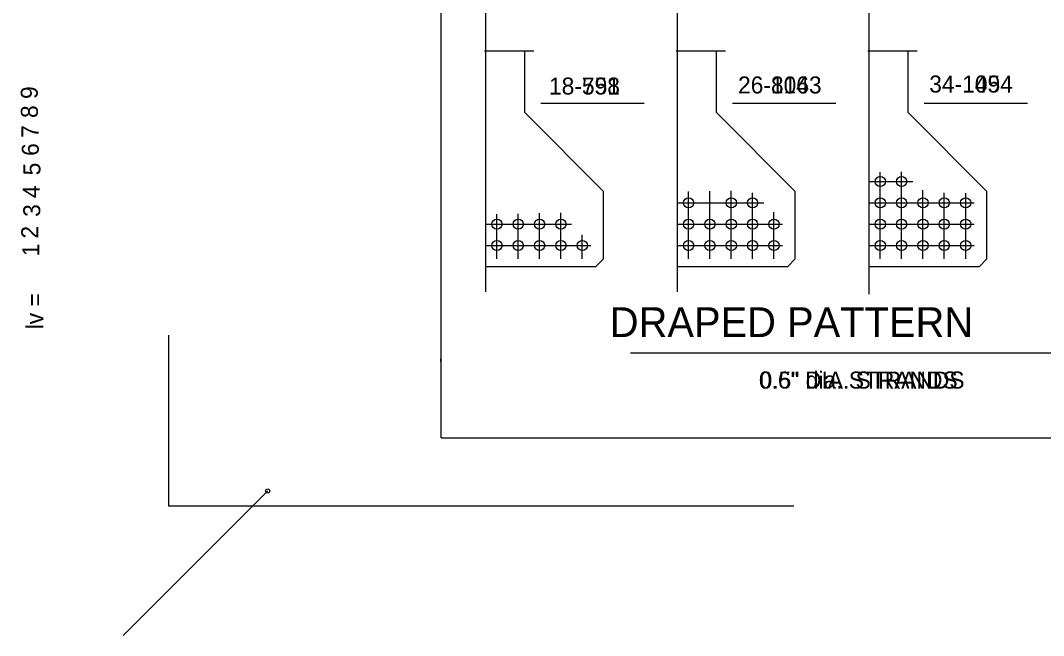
# Model space of a CAD drawing. Extents: x 1005.3 to 1101.9, y 1996.5 to 2073.3.
# Drawn here: x 1005.62 to 1025.64, y 2008.29 to 2020.32 of the extents above; entities that cross this region are included whole.
import ezdxf

# ---------------------------------------------------------------- set-up
doc = ezdxf.new("R2010")
doc.units = 0
for name, color, linetype in [('Level 1', 7, 'Continuous'), ('Level 2', 7, 'Continuous'), ('Level 3', 7, 'Continuous'), ('Level 4', 7, 'Continuous'), ('Level 49', 7, 'Continuous'), ('Level 5', 7, 'Continuous'), ('Level 6', 7, 'Continuous'), ('Level 7', 7, 'Continuous'), ('Level 8', 7, 'Continuous'), ('Level 9', 7, 'Continuous')]:
    doc.layers.add(name, color=color, linetype=linetype)

msp = doc.modelspace()

# ---------------------------------------------------------------- linework, layer by layer
at = {"layer": 'Level 1'}
for p, q in [((1013.852, 2012.158), (1013.852, 2068.156)), ((1008.518, 2014.165), (1008.518, 2010.825)), ((1013.84, 2013.698), (1013.84, 2013.64)), ((1013.852, 2012.158), (1097.517, 2012.158)), ((1008.518, 2010.825), (1020.752, 2010.825))]:
    msp.add_line(p, q, dxfattribs=at)
at = {"layer": 'Level 2'}
for p, q in [((1017.555, 2013.82), (1026.098, 2013.82)), ((1007.632, 2008.287), (1010.461, 2011.116))]:
    msp.add_line(p, q, dxfattribs=at)
at = {"layer": 'Level 49'}
msp.add_circle((1010.46, 2011.116), 0.0405, dxfattribs=at)
at = {"layer": 'Level 8'}
for p, q in [((1014.726, 2015.012), (1014.726, 2037.24)), ((1018.476, 2015.012), (1018.476, 2037.24)), ((1022.226, 2014.966), (1022.226, 2037.289)), ((1014.703, 2019.726), (1015.668, 2019.726)), ((1015.488, 2018.518), (1015.488, 2019.719)), ((1018.453, 2019.726), (1019.418, 2019.726)), ((1019.238, 2018.518), (1019.238, 2019.719)), ((1022.203, 2019.726), (1023.168, 2019.726)), ((1022.988, 2018.518), (1022.988, 2019.719)), ((1015.804, 2018.702), (1017.824, 2018.702)), ((1019.554, 2018.702), (1021.574, 2018.702)), ((1023.304, 2018.702), (1025.324, 2018.702)), ((1017.032, 2016.973), (1015.488, 2018.518)), ((1020.782, 2016.973), (1019.238, 2018.518)), ((1024.532, 2016.973), (1022.988, 2018.518)), ((1022.226, 2017.172), (1023.082, 2017.172)), ((1022.445, 2015.658), (1022.445, 2017.352)), ((1022.862, 2015.658), (1022.862, 2017.358)), ((1017.032, 2015.658), (1017.032, 2016.973)), ((1018.695, 2015.658), (1018.695, 2016.976)), ((1019.112, 2015.658), (1019.112, 2016.982)), ((1019.53, 2015.658), (1019.53, 2016.989)), ((1020.782, 2015.658), (1020.782, 2016.973)), ((1023.28, 2015.658), (1023.28, 2017)), ((1024.532, 2015.658), (1024.532, 2016.973)), ((1019.947, 2015.658), (1019.947, 2016.952)), ((1023.697, 2015.658), (1023.697, 2016.952)), ((1024.115, 2015.658), (1024.115, 2016.944)), ((1018.476, 2016.754), (1020.168, 2016.754)), ((1020.365, 2015.658), (1020.365, 2016.57)), ((1022.226, 2016.754), (1024.283, 2016.754)), ((1014.945, 2015.658), (1014.945, 2016.529)), ((1015.362, 2015.658), (1015.362, 2016.538)), ((1015.78, 2015.658), (1015.78, 2016.548)), ((1016.197, 2015.658), (1016.197, 2016.557)), ((1014.726, 2016.337), (1016.401, 2016.337)), ((1018.476, 2016.337), (1020.533, 2016.337)), ((1022.226, 2016.337), (1024.283, 2016.337)), ((1016.615, 2015.658), (1016.615, 2016.127)), ((1014.726, 2015.919), (1016.783, 2015.919)), ((1018.476, 2015.919), (1020.533, 2015.919)), ((1022.226, 2015.919), (1024.283, 2015.919)), ((1016.876, 2015.501), (1017.032, 2015.658)), ((1020.626, 2015.501), (1020.782, 2015.658)), ((1024.376, 2015.501), (1024.532, 2015.658)), ((1016.876, 2015.501), (1014.726, 2015.501)), ((1020.626, 2015.501), (1018.476, 2015.501)), ((1024.376, 2015.501), (1022.226, 2015.501))]:
    msp.add_line(p, q, dxfattribs=at)
for centre in [(1022.445, 2017.172), (1022.862, 2017.172), (1018.695, 2016.754), (1019.53, 2016.754), (1019.947, 2016.754), (1022.445, 2016.754), (1022.862, 2016.754), (1023.28, 2016.754), (1023.697, 2016.754), (1024.115, 2016.754), (1014.945, 2016.337), (1015.362, 2016.337), (1015.78, 2016.337), (1016.197, 2016.337), (1018.695, 2016.337), (1019.112, 2016.337), (1019.53, 2016.337), (1019.947, 2016.337), (1020.365, 2016.337), (1022.445, 2016.337), (1022.862, 2016.337), (1023.28, 2016.337), (1023.697, 2016.337), (1024.115, 2016.337), (1014.945, 2015.919), (1015.362, 2015.919), (1015.78, 2015.919), (1016.197, 2015.919), (1016.615, 2015.919), (1018.695, 2015.919), (1019.112, 2015.919), (1019.53, 2015.919), (1019.947, 2015.919), (1020.365, 2015.919), (1022.445, 2015.919), (1022.862, 2015.919), (1023.28, 2015.919), (1023.697, 2015.919), (1024.115, 2015.919)]:
    msp.add_circle(centre, 0.0996, dxfattribs=at)
at = {"layer": 'Level 9'}
for p, q in [((1014.726, 2015.012), (1014.726, 2037.24)), ((1018.476, 2015.012), (1018.476, 2037.24)), ((1022.226, 2014.966), (1022.226, 2037.289)), ((1014.703, 2019.726), (1015.668, 2019.726)), ((1015.488, 2018.518), (1015.488, 2019.719)), ((1018.453, 2019.726), (1019.418, 2019.726)), ((1019.238, 2018.518), (1019.238, 2019.719)), ((1022.203, 2019.726), (1023.168, 2019.726)), ((1022.988, 2018.518), (1022.988, 2019.719)), ((1015.804, 2018.702), (1017.824, 2018.702)), ((1019.554, 2018.702), (1021.574, 2018.702)), ((1023.304, 2018.702), (1025.324, 2018.702)), ((1017.032, 2016.973), (1015.488, 2018.518)), ((1020.782, 2016.973), (1019.238, 2018.518)), ((1024.532, 2016.973), (1022.988, 2018.518)), ((1022.226, 2017.172), (1023.082, 2017.172)), ((1022.445, 2015.658), (1022.445, 2017.352)), ((1022.862, 2015.658), (1022.862, 2017.358)), ((1017.032, 2015.658), (1017.032, 2016.973)), ((1018.695, 2015.658), (1018.695, 2016.976)), ((1019.112, 2015.658), (1019.112, 2016.982)), ((1019.53, 2015.658), (1019.53, 2016.989)), ((1020.782, 2015.658), (1020.782, 2016.973)), ((1023.28, 2015.658), (1023.28, 2017)), ((1024.532, 2015.658), (1024.532, 2016.973)), ((1019.947, 2015.658), (1019.947, 2016.952)), ((1023.697, 2015.658), (1023.697, 2016.952)), ((1024.115, 2015.658), (1024.115, 2016.944)), ((1018.476, 2016.754), (1020.168, 2016.754)), ((1020.365, 2015.658), (1020.365, 2016.57)), ((1022.226, 2016.754), (1024.283, 2016.754)), ((1014.945, 2015.658), (1014.945, 2016.529)), ((1015.362, 2015.658), (1015.362, 2016.538)), ((1015.78, 2015.658), (1015.78, 2016.548)), ((1016.197, 2015.658), (1016.197, 2016.557)), ((1014.726, 2016.337), (1016.401, 2016.337)), ((1018.476, 2016.337), (1020.533, 2016.337)), ((1022.226, 2016.337), (1024.283, 2016.337)), ((1016.615, 2015.658), (1016.615, 2016.127)), ((1014.726, 2015.919), (1016.783, 2015.919)), ((1018.476, 2015.919), (1020.533, 2015.919)), ((1022.226, 2015.919), (1024.283, 2015.919)), ((1016.876, 2015.501), (1017.032, 2015.658)), ((1020.626, 2015.501), (1020.782, 2015.658)), ((1024.376, 2015.501), (1024.532, 2015.658)), ((1016.876, 2015.501), (1014.726, 2015.501)), ((1020.626, 2015.501), (1018.476, 2015.501)), ((1024.376, 2015.501), (1022.226, 2015.501))]:
    msp.add_line(p, q, dxfattribs=at)
for centre in [(1022.445, 2017.172), (1022.862, 2017.172), (1018.695, 2016.754), (1019.53, 2016.754), (1019.947, 2016.754), (1022.445, 2016.754), (1022.862, 2016.754), (1023.28, 2016.754), (1023.697, 2016.754), (1024.115, 2016.754), (1014.945, 2016.337), (1015.362, 2016.337), (1015.78, 2016.337), (1016.197, 2016.337), (1018.695, 2016.337), (1019.112, 2016.337), (1019.53, 2016.337), (1019.947, 2016.337), (1020.365, 2016.337), (1022.445, 2016.337), (1022.862, 2016.337), (1023.28, 2016.337), (1023.697, 2016.337), (1024.115, 2016.337), (1014.945, 2015.919), (1015.362, 2015.919), (1015.78, 2015.919), (1016.197, 2015.919), (1016.615, 2015.919), (1018.695, 2015.919), (1019.112, 2015.919), (1019.53, 2015.919), (1019.947, 2015.919), (1020.365, 2015.919), (1022.445, 2015.919), (1022.862, 2015.919), (1023.28, 2015.919), (1023.697, 2015.919), (1024.115, 2015.919)]:
    msp.add_circle(centre, 0.0996, dxfattribs=at)

# ---------------------------------------------------------------- texts
at = {"layer": 'Level 1'}
msp.add_text('1', height=0.333, rotation=90, dxfattribs=at).set_placement((1005.99, 2015.707))
at = {"layer": 'Level 2'}
for s, height, p in [('2', 0.333, (1005.971, 2016.054)), ('lv =', 0.3333, (1006.068, 2014.278))]:
    msp.add_text(s, height=height, rotation=90, dxfattribs=at).set_placement(p)
msp.add_text('  DRAPED PATTERN', height=0.58333, dxfattribs=at).set_placement((1016.719, 2014.127))
at = {"layer": 'Level 3'}
msp.add_text('3', height=0.333, rotation=90, dxfattribs=at).set_placement((1006.01, 2016.479))
at = {"layer": 'Level 4'}
msp.add_text('4', height=0.333, rotation=90, dxfattribs=at).set_placement((1006.001, 2016.846))
at = {"layer": 'Level 5'}
msp.add_text('5', height=0.333, rotation=90, dxfattribs=at).set_placement((1006.013, 2017.291))
at = {"layer": 'Level 6'}
msp.add_text('6', height=0.333, rotation=90, dxfattribs=at).set_placement((1005.982, 2017.672))
at = {"layer": 'Level 7'}
msp.add_text('7', height=0.333, rotation=90, dxfattribs=at).set_placement((1005.976, 2018.025))
at = {"layer": 'Level 8'}
for s, height, p in [('18-558 ', 0.3333, (1015.963, 2018.872)), ('26-806 ', 0.3333, (1019.661, 2018.893)), ('34-1054 ', 0.3333, (1023.402, 2018.911)), ('0.5" dia. STRANDS', 0.33333, (1020.084, 2013.119))]:
    msp.add_text(s, height=height, dxfattribs=at).set_placement(p)
msp.add_text('8', height=0.333, rotation=90, dxfattribs=at).set_placement((1005.964, 2018.413))
at = {"layer": 'Level 9'}
for s, height, p in [('18-791', 0.3333, (1015.963, 2018.872)), ('26-1143', 0.3333, (1019.661, 2018.893)), ('34-1494', 0.3333, (1023.402, 2018.911)), ('0.6" DIA. STRANDS', 0.33333, (1020.07, 2013.119))]:
    msp.add_text(s, height=height, dxfattribs=at).set_placement(p)
msp.add_text('9', height=0.333, rotation=90, dxfattribs=at).set_placement((1005.961, 2018.785))

doc.saveas('drawing.dxf')
